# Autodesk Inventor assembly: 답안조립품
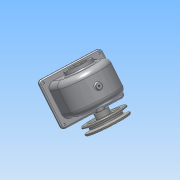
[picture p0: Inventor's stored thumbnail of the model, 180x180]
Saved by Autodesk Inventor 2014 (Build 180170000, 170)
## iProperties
Created: 2016-01
Part Number: 답안조립품
Document SubType Name: Assembly
Designer: net
Author: net
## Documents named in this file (10)
- C:\Users\net\Desktop\460105V1030\답안조립품.iam
- C:\Users\net\Desktop\460105V1030\본체.ipt
- C:\Users\net\Desktop\460105V1030\베어링 6203.ipt
- C:\Users\net\Desktop\460105V1030\스퍼기어.ipt
- C:\Users\net\Desktop\460105V1030\축.ipt
- C:\Users\net\Desktop\460105V1030\부시1.ipt
- C:\Users\net\Desktop\460105V1030\키 - 6 x 6 x 22.ipt
- C:\Users\net\Desktop\460105V1030\키 - 5 x 5 x 18.ipt
- C:\Users\net\Desktop\460105V1030\V-벨트풀리.ipt
- C:\Users\net\Desktop\460105V1030\멈춤나사 - M4x10.ipt
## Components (1 placed, 1 different names)
1. V-벨트풀리:1 — 각도:4
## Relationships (1: Angle 1)
- 각도:4 [Angle]: V-벨트풀리:1
